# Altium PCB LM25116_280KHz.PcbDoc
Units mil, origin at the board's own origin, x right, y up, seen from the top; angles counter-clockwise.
Board outline 2245 x 1195 mil, 2 copper layers (Top Layer, Bottom Layer); 35 components, 23 nets, 91 pads, 238 vias.
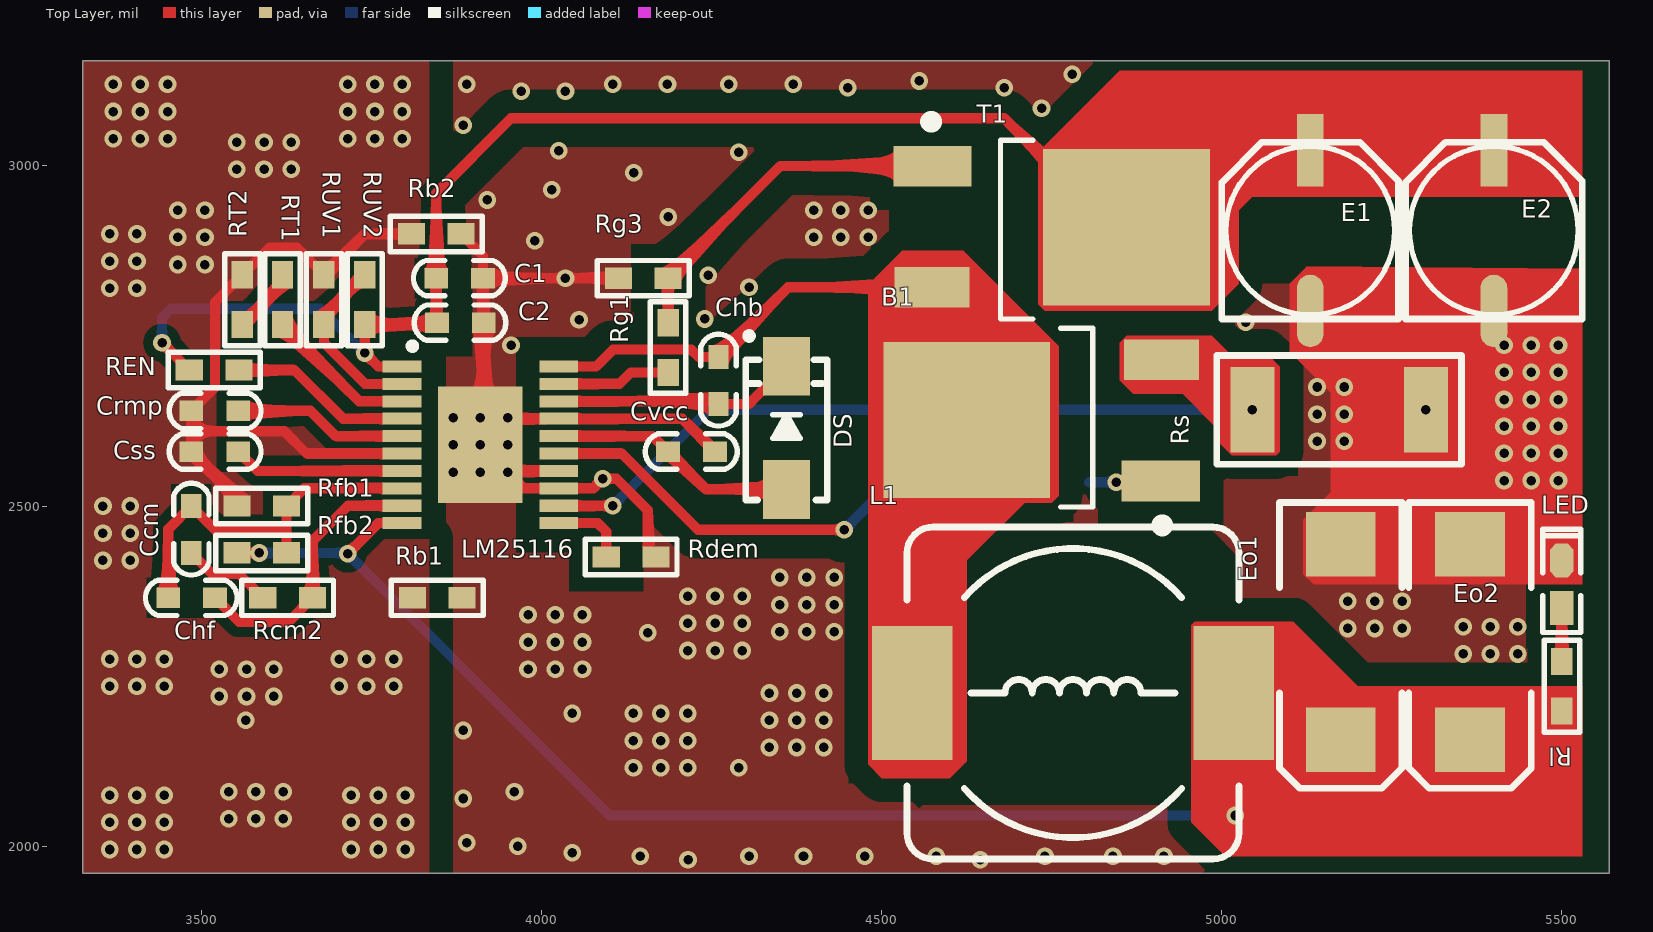
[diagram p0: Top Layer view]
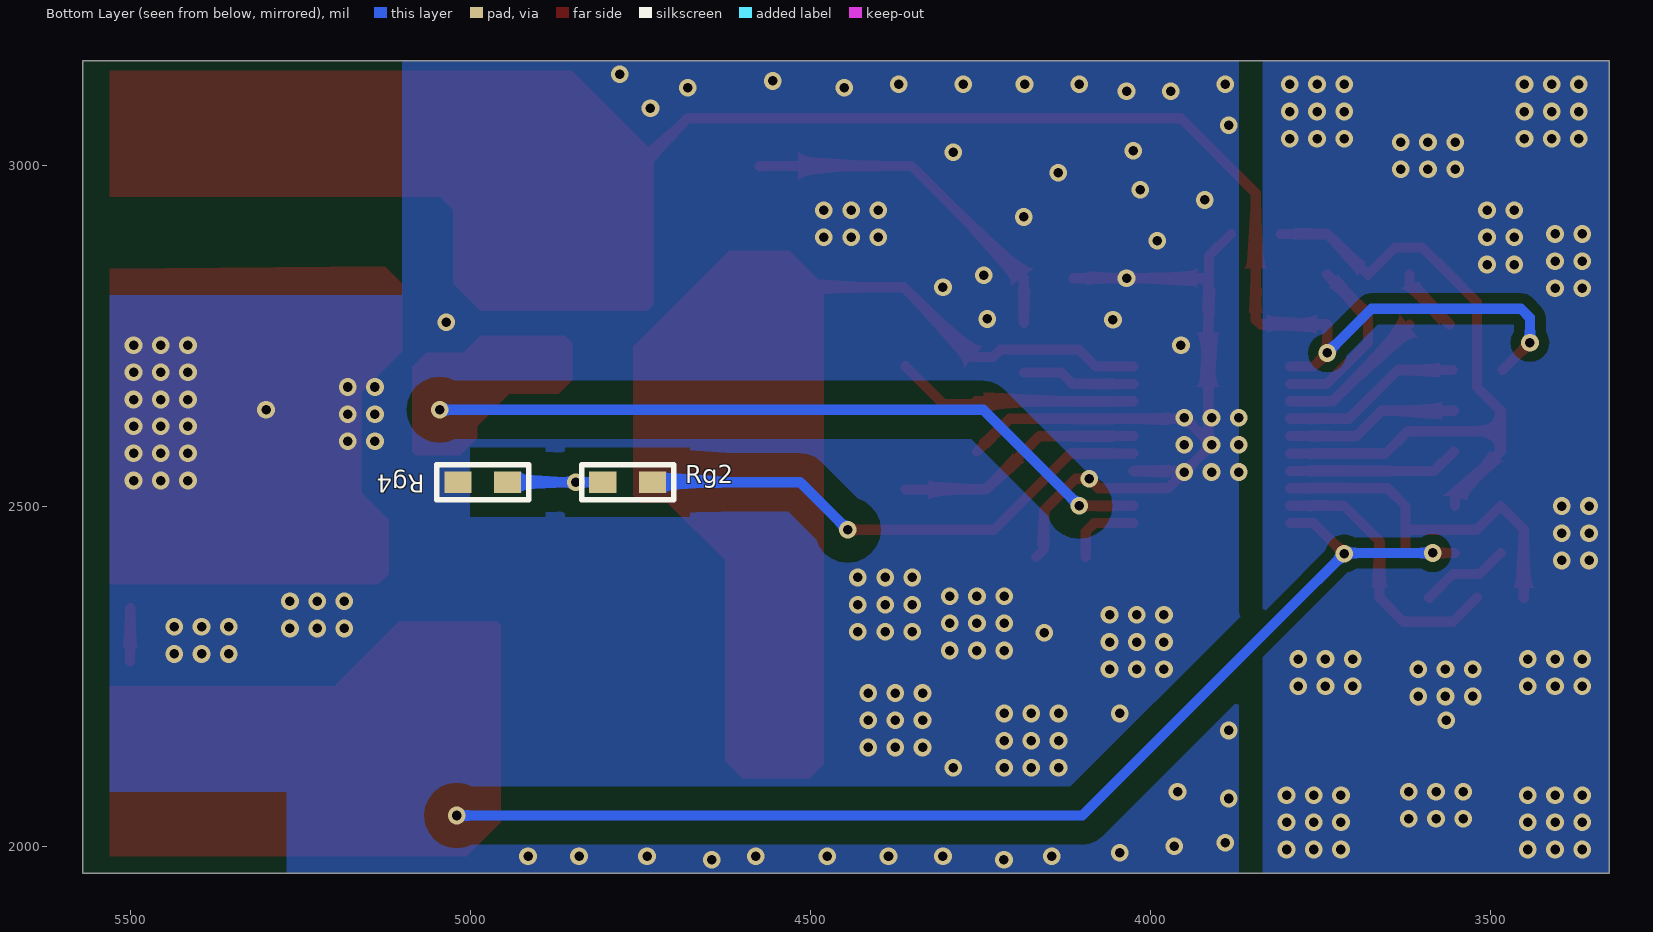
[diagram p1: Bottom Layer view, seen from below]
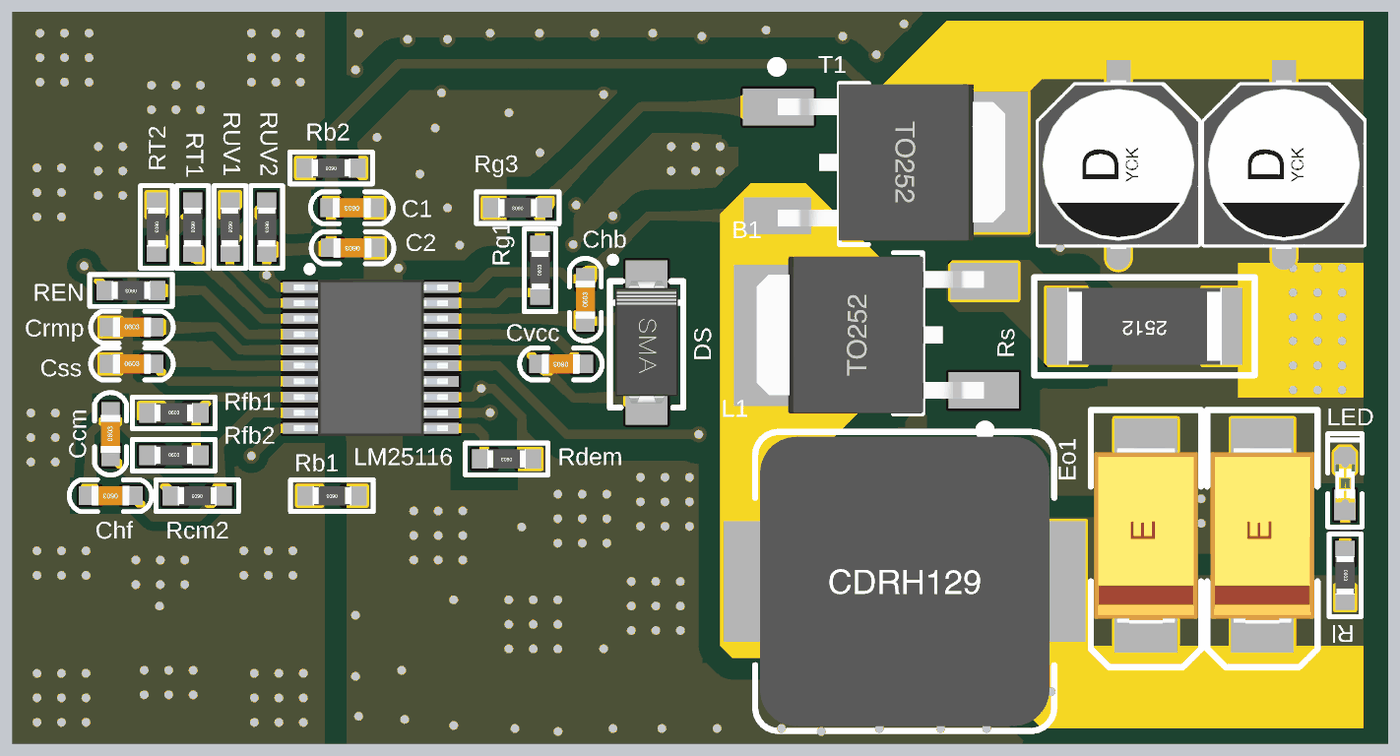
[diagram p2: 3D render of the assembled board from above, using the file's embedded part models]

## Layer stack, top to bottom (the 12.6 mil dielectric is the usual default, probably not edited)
Top Solder: solder mask 0.4, Solder Resist, Dk 3.5
Top Layer: signal copper 1.4
Dielectric 1: dielectric 12.6, FR-4, Dk 4.8
Bottom Layer: signal copper 1.4
Bottom Solder: solder mask 0.4, Solder Resist, Dk 3.5

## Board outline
3325,1960 3325,3155 5570,3155 5570,1960

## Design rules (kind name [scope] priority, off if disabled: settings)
Clearance Clearance_PGND_Ploygon [(InNamedPolygon('PGND_B') OR InNamedPolygon('PGND_T'))] p1: gap=35 ignorepadtopadclearanceinfootprint=FALSE
Clearance Clearance_AGND_Ploygon [(InNamedPolygon('AGND_B') OR InNamedPolygon('AGND_T'))] p2: gap=15 ignorepadtopadclearanceinfootprint=FALSE
Clearance Clearance_wire [All] p3: gap=5 ignorepadtopadclearanceinfootprint=FALSE
PolygonConnect [All] p1: connectstyle=Direct reliefconductorwidth=10 reliefentries=4 polygonreliefangle="90 Angle" airgapwidth=10
RoutingVias [All] p1: holewidth=28 width=50 viastyle="Through Hole" minholewidth=12 minwidth=24 maxholewidth=2800 maxwidth=5000
SolderMaskExpansion [All] p1: expansion=4
Width [All] p1: maxlimit=1000 minlimit=5 preferedwidth=10
30 further rules are at their usual default settings.

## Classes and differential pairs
polygon class PolygonClass_PGND: PGND_B PGND_T
polygon class PolygonClass_AGND: AGND_B AGND_T

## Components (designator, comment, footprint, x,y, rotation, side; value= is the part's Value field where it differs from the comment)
B1 "NTD5C668NLT4G" TO252 4790.35,2626.5 r90 top
C1 "0.1uF" "C 0603" 3879,2835 r180 top
C2 "0.1uF" "C 0603" 3880,2769.5 r180 top
Ccm "1.2nF" "C 0603" 3485,2466 r90 top
Chb "150n" "C 0603" 4260,2685 r90 top
Chf "47pF" "C 0603" 3485,2365 r180 top
Crmp "180pF" "C 0603" 3520,2640 r0 top
Css "4.7nF" "C 0603" 3520,2580 r0 top
Cvcc "330n" "C 0603" 4220,2580 r180 top
DS "SS24" SMA 4360,2615 r90 top
E1 "47uF/50V" "CM D(6.3*7.7)" 5130,2905 r90 top
E2 "47uF/50V" "CM D(6.3*7.7)" 5400,2905 r90 top
Eo1 "470uF/6.3V" "CD E(7343H)" 5175,2300 r90 top
Eo2 "470uF/6.3V" "CD E(7343H)" 5365,2300 r90 top
L1 "1uH" CDRH129 4781.22,2225 r0 top
LED "红色" "LED 0603R" 5500,2385 r90 top
LM25116 "LM25116" HSSOP20 3910,2585 r0 top
Rb1 "0" "R 0603" 3846.5,2365 r180 top
Rb2 "0" "R 0603" 3845,2900 r180 top
Rcm2 "82K" "R 0603" 3626.5,2365 r180 top
Rdem "10K" "R 0603" 4131.5,2425 r180 top
REN "1M" "R 0603" 3518.5,2700 r180 top
Rfb1 "10K" "R 0603" 3588.5,2500 r0 top
Rfb2 "32.4K" "R 0603" 3588.5,2431 r0 top
Rg1 "0" "R 0603" 4186,2733 r90 top
Rg2 "0" "R 0603" 4768.5,2535 r0 bottom
Rg3 "1M" "R 0603" 4149.5,2835 r180 top
Rg4 "1M" "R 0603" 4981.5,2535 r180 bottom
Rl "10K" "R 0603" 5500,2235 r270 top
Rs "3m" "R 2512" 5172.56,2641.5 r180 top
RT1 "10K" "R 0603" 3618.98,2803.39 r270 top
RT2 "1K" "R 0603" 3560,2803.39 r270 top
RUV1 "38.3K" "R 0603" 3679.95,2803.39 r270 top
RUV2 "180K" "R 0603" 3740,2803.39 r270 top
T1 "NTD5C668NLT4G" TO252 4694.65,2910 r270 top

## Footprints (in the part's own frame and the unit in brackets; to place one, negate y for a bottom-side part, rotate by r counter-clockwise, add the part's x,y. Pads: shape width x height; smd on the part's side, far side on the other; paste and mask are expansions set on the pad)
"C 0603" [mil] "无极性贴片电容"
  rect 35x30 smd: 1(-35,0) 2(34,0)
  silkscreen extent -67,-26 67,26, body extent -31,-16 31,16, height 32
"CD E(7343H)" [mm] "长7.3mm，宽4.3mm，厚4.0mm"
  rect 2.4x2.6 smd: 1(-3.65,0) 2(3.65,0)
  silkscreen extent -5.46,-2.29 5.21,2.29, body extent -3.65,-2.15 3.65,2.15, height 4
CDRH129 [mm] "12*12*9.5mm（长宽高）"
  rect 3x5 smd: 1(-6,0) 2(6,0)
  silkscreen extent -6.2,-6.2 6.2,6.2, body extent -6,-6 6,6, height 9.65
"CM D(6.3*7.7)" [mm] "贴片电解电容，直径6.3mm，高7.7mm"
  rect 2.7x1 smd: 1(3,0)
  oval 2.7x1 smd: 2(-3,0)
  silkscreen extent -3.3,-3.3 3.3,3.3, body extent -3.5,-3.3 3.5,3.3, height 7.7
HSSOP20 [mm]
  rect 1.45x0.45 smd: 1(-2.925,3.052) 2(-2.925,2.402) 3(-2.925,1.752) 4(-2.925,1.102) 5(-2.925,0.452) 6(-2.925,-0.198) 7(-2.925,-0.848) 8(-2.925,-1.498) 9(-2.925,-2.148) 10(-2.925,-2.798) 11(2.925,-2.798) 12(2.925,-2.148) 13(2.925,-1.498) 14(2.925,-0.848) 15(2.925,-0.198) 16(2.925,0.452) 17(2.925,1.102) 18(2.925,1.752) 19(2.925,2.402) 20(2.925,3.052)
  rect 3.15x4.35 smd: 21(0,0.127)
  silkscreen extent -2.67,3.68 -2.41,3.94, body extent -3.2,-3.12 3.2,3.38, height 1.1
"LED 0603R" [mil] "红色0603LED"
  rect 50x35 smd: 1(-35,0.26)
  oct 50x35 smd: 2(35,0.26)
  silkscreen extent -71,-28 81,28, body extent -31,-16 32,16, height 24
"R 0603" [mil] "1/10W贴片电阻"
  rect 40x31.5 smd: 1(-36.5,0) 2(36.5,0)
  silkscreen extent -68,-26 68,26, body extent -31,-16 32,16, height 16
"R 2512" [mm] "1W贴片电阻"
  rect 1.65x3.2 smd: 1(-3.24,0) 2(3.24,0)
  silkscreen extent -4.57,-2.03 4.57,2.03, body extent -3.2,-1.6 3.2,1.6, height 0.55
SMA [mm] "4.5x2.6*2.2mm（长宽高，不包括引脚）"
  rect 2.2x1.75 smd: 1(-2.3,0) 2(2.3,0)
  silkscreen extent -2.7,-1.52 3.56,1.52, body extent -2.53,-1.3 2.58,1.3, height 2.15
TO252 [mil] "252晶体管"
  rect 60x115 smd: 1(-89.55,-119.77)
  rect 230x245 smd: 2(0,165.35)
  rect 60x110 smd: 3(88.45,-120.77)
  silkscreen extent -156,-123 135,28, body extent -127,-120 129,251, height 91

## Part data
B1 T1: library part 2SK3615, "N沟场效应管"
C1 C2 Ccm Chb Chf Crmp Css Cvcc: library part C, "无极性贴片电容"
DS: library part SS14, "肖特基二极管"
E1 E2: library part C-CM, "贴片电解电容"
Eo1 Eo2: library part C-CD, "贴片钽电容"
L1: library part L-CDRH, "功率屏蔽电感"
LED: library part LED-SMD, "贴片LED"
LM25116: "42V 宽输入电压同步降压控制器"
Rb1 Rb2 Rcm2 Rdem REN Rfb1 Rfb2 Rg1 Rg2 Rg3 Rg4 Rl Rs RT1 RT2 RUV1 RUV2: library part R, "贴片电阻"

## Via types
v1: diameter 26, hole 14, Top Layer to Bottom Layer, tented both sides, 238 vias

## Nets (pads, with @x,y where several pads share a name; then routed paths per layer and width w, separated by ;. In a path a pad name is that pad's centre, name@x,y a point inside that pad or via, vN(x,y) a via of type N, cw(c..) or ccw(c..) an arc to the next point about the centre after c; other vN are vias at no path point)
+5: Eo1.1 Eo2.1 L1.2 LM25116.10 Rfb2.1 Rl.2 | length 1726.3
  Top Layer w15: Rfb2.1 v1(3585,2431) ; v1(3715,2430) 3759.84,2474.84 LM25116.10
  Bottom Layer w15: v1(3585,2431) 3714,2431 v1(3715,2430) 3795,2350 4100,2045 v1(5020,2045)
AGND: Crmp.1 Css.1 LM25116.6 Rb1.2 Rb2.2 Rfb1.1 RT2.1 RUV1.1 | length 1028.8
  Top Layer w15: Rfb1.1 3552,2513 Css.1 3485,2610 ; LM25116.6 3654.3,2577.2 3621.5,2610 3485,2610 ; Rb2.2 3740.06,2900 RUV1.1 3639.84,2880 3600.11,2880 RT2.1 3520,2799.89 3520,2675 Crmp.1 3485,2610
  other v1: 3365,1995 3405,1995 3445,1995 3719.84,1995 3759.84,1995 3799.84,1995 3365,2035 3405,2035 3445,2035 3719.84,2035 3759.84,2035 3799.84,2035 3540,2040 3580,2040 3620,2040 3365,2075 3405,2075 3445,2075 3719.84,2075 3759.84,2075 3799.84,2075 3540,2080 3580,2080 3620,2080 3565,2185 3526.16,2220 3566.16,2220 3606.16,2220 3365,2235 3405,2235 3445,2235 3702.6,2235 3742.6,2235 3782.6,2235 3526.16,2260 3566.16,2260 3606.16,2260 3365,2275 3405,2275 3445,2275 3702.6,2275 3742.6,2275 3782.6,2275 3355,2420 3395,2420 3355,2460 3395,2460 3355,2500 3395,2500 3365,2820 3405,2820 3465,2855 3505,2855 3365,2860 3405,2860 3465,2895 3505,2895 3365,2900 3405,2900 3465,2935 3505,2935 3551.89,2995 3591.89,2995 3631.89,2995 3551.89,3035 3591.89,3035 3631.89,3035 3370,3040 3410,3040 3450,3040 3715,3040 3755,3040 3795,3040 3370,3080 3410,3080 3450,3080 3715,3080 3755,3080 3795,3080 3370,3120 3410,3120 3450,3120 3715,3120 3755,3120 3795,3120
COMP: Chf.1 LM25116.9 Rcm2.1 | length 408.6
  Top Layer w15: Chf.1 3555,2330 3628,2330 Rcm2.1 3663,2448.13 3715.31,2500.43 LM25116.9
CS: B1.3 LM25116.12 Rs.2 | length 1078.3
  Top Layer w15: LM25116.12 v1(4104.57,2500.43)
  Bottom Layer w15: v1(4104.57,2500.43) 4245.63,2641.5 v1(5045,2641.5)
CSG: C1.1 C2.1 Cvcc.1 E1.2 E2.2 Eo1.2 Eo2.2 LED.2 LM25116.13 LM25116.14 LM25116.17 LM25116.21 Rb1.1 Rb2.1 Rdem.1 Rg3.2 Rg4.1 Rs.1 | length 1346.9
  Top Layer w15: Rb2.1 3914,2867.5 C1.1 ; LM25116.14 LM25116.21@3948.39,2551.61 ; Rg3.2 v1(4035,2835) C1.1 ; Rdem.1 4156.19,2436.81 4156.19,2493.81 4110,2540 v1(4090,2540) 4076.02,2526.02 LM25116.13 3973.98,2526.02 v1(3950,2550) LM25116.21@3948.39,2551.61 ; Cvcc.1 4206.61,2628.39 LM25116.17 3948.39,2628.39 LM25116.21@3915,2595 ; C1.1 3914,2770.5 C2.1 LM25116.21@3915,2595 ; LM25116.21@3915,2595 v1(3910,2590) LM25116.21@3948.39,2551.61
  other v1: 4215.32,1980 4645,1980 4145,1985 4305,1985 4385,1985 4475,1985 4580,1985 4740,1985 4840,1985 4915,1985 4045,1990 3965,2000 3890,2005 3885,2070 3960,2080 4135,2115 4175,2115 4215,2115 4290,2115 4335,2145 4375,2145 4415,2145 4135,2155 4175,2155 4215,2155 3885,2170 4335,2185 4375,2185 4415,2185 4045,2195 4135,2195 4175,2195 4215,2195 4335,2225 4375,2225 4415,2225 3980,2260 4020,2260 4060,2260 5355,2282.5 5395,2282.5 5435,2282.5 4215,2287.5 4255,2287.5 4295,2287.5 3980,2300 4020,2300 4060,2300 4156.19,2313.78 4350,2314.96 4390,2314.96 4430,2314.96 5185,2320 5225,2320 5265,2320 5355,2322.5 5395,2322.5 5435,2322.5 4215,2327.5 4255,2327.5 4295,2327.5 3980,2340 4020,2340 4060,2340 4350,2354.96 4390,2354.96 4430,2354.96 5185,2360 5225,2360 5265,2360 4215,2367.5 4255,2367.5 4295,2367.5 4350,2394.96 4390,2394.96 4430,2394.96 5415,2537.5 5455,2537.5 5495,2537.5 3870,2550 3910,2550 5415,2577.5 5455,2577.5 5495,2577.5 3870,2590 3950,2590 5140,2595 5180,2595 5415,2617.5 5455,2617.5 5495,2617.5 3870,2630 3910,2630 3950,2630 5140,2635 5180,2635 5300.12,2641.5 5415,2656.5 5455,2656.5 5495,2656.5 5140,2675 5180,2675 5415,2696.5 5455,2696.5 5495,2696.5 3955,2736.5 5415,2736.5 5455,2736.5 5495,2736.5 5035,2770 4055,2774 4240,2775 4305,2821.55 4245,2839.39 3990,2890 4400,2895 4440,2895 4480,2895 4186,2925 4400,2935 4440,2935 4480,2935 3920,2950 4015,2965 4135.25,2990 4290,3020 4025.16,3022.51 3885,3060 4735,3085 3970,3110 4035,3110 4450,3115 4680,3115 3890,3120 4104.57,3120 4185,3120 4275,3120 4370,3120 4555,3125 4780,3135
DEMB: LM25116.11 Rdem.2 | length 112.5
  Top Layer w15: LM25116.11 4082.66,2474.84 4095,2462.5 Rdem.2
EN: LM25116.4 REN.1 | length 269.5
  Top Layer w15: REN.1 3636.5,2700 3708.11,2628.39 LM25116.4
FB: Ccm.2 Chf.2 LM25116.8 Rfb1.2 Rfb2.2 | length 553.4
  Top Layer w15: Chf.2 3451,2466 Ccm.2 3520,2465 3624.5,2465 3625,2465.5 ; Rfb2.2 3625,2465.5 ; LM25116.8 3651.02,2526.02 Rfb1.2 3625,2465.5
HB: Chb.1 DS.2 LM25116.18 | length 359.5
  Top Layer w15: LM25116.18 4256.02,2653.98 Chb.1 4304.45,2650 DS.2
HO: LM25116.19 Rg1.1 | length 167.9
  Top Layer w15: LM25116.19 4114.57,2679.57 4131.5,2696.5 Rg1.1
LO: LM25116.15 Rg2.1 | length 782.3
  Top Layer w15: LM25116.15 4117.8,2577.2 4230,2465 v1(4445,2465)
  Bottom Layer w15: v1(4445,2465) 4515,2535 Rg2.1
NetB1_1: B1.1 Rg2.2 Rg4.2 | length 205.9
  Top Layer w15: v1(4845,2535) 4908.18,2535 B1.1
  Bottom Layer w15: Rg2.2 v1(4845,2535) Rg4.2
NetCcm_1: Ccm.1 Rcm2.2 | length 132.3
  Top Layer w15: Ccm.1 3516,2400 3555,2400 Rcm2.2
NetLED_1: LED.1 Rl.1 | length 79.1
  Top Layer w15: LED.1 5499.74,2286.24 5500,2286.5 Rl.1
NetRg1_2: Rg1.2 Rg3.1 T1.1 | length 522.9
  Top Layer w15: Rg1.2 Rg3.1 4351,3000 4574.43,3000 T1.1
NetRT1_1: RT1.1 RT2.2 | length 97.4
  Top Layer w15: RT2.2 3618.98,2825.87 RT1.1
RAMP: Crmp.2 LM25116.5 | length 256.3
  Top Layer w15: Crmp.2 3660,2640 3697.2,2602.8 LM25116.5
RT/SYNC: LM25116.3 RT1.2 | length 222.6
  Top Layer w15: RT1.2 3731.89,2653.98 LM25116.3
SS: Css.2 LM25116.7 | length 252.6
  Top Layer w15: Css.2 3582.39,2551.61 LM25116.7
SW: B1.2 Chb.2 L1.1 LM25116.20 T1.3 | length 606
  Top Layer w15: LM25116.20 4080.16,2705.16 4105,2730 4220,2730 4231,2719 Chb.2 4362.55,2821.55 T1.3
UVLO: LM25116.2 RUV1.2 RUV2.1 | length 264.7
  Top Layer w15: RUV2.1 3679.95,2779.84 RUV1.2 3679.95,2740 3740.38,2679.57 LM25116.2
VCC: C1.2 C2.2 E1.1 E2.1 LM25116.1 REN.2 RUV2.2 T1.2 | length 1949.6
  Top Layer w15: v1(3442,2740) REN.2 ; LM25116.1 3759.84,2705.16 v1(3740,2725) RUV2.2 3837.89,2766.89 3845,2774 C1.2 3845,2960 3955,3070 4680,3070 4840,2910 T1.2
  Bottom Layer w15: v1(3442,2740) 3442,2777 3455,2790 3675,2790 v1(3740,2725)
VCC_G: Cvcc.2 DS.1 LM25116.16 | length 367.3
  Top Layer w15: LM25116.16 4163.2,2602.8 Cvcc.2 4241.55,2524.45 DS.1

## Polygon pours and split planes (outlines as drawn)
CSG on Top Layer "PGND_T" (solid, remove dead copper, pour order 4): 3860,3155 3860,1960 5530,1960 5530,3155
AGND on Top Layer "AGND_T" (solid, remove dead copper, pour order 0): 3325,3155 3325,1960 3835,1960 3835,3155
CSG on Bottom Layer "PGND_B" (solid, remove dead copper, pour order 6): 3860,3155 3860,1960 5530,1960 5530,3155
AGND on Bottom Layer "AGND_B" (solid, remove dead copper, pour order 2): 3325,3155 3325,1960 3835,1960 3835,3155

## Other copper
Top Layer:
  pour cut-out: 5060.3,2919.7 5060.3,2826.89 5530,2826.89 5530,2919.7
  pour cut-out: 5060.3,2919.7
  pour cut-out: 4510,3035 4510,2845 4710,2845 4710,3035
  pour cut-out: 4545,2426 4545,2065 4555,2055 4560,2060 4995,2060 5025,2090 5025,2425 4985,2465 4583.86,2465
  region net AGND: 3325,3155
  region net CSG: 5125,2852.5 5125,2851.89 5100,2826.89 5100,2726.5 5160,2666.5 5160,2520 5120,2480 5120,2400 5135,2385 5530,2385 5530,2849.07
  region net +5: 4960,2330 4955,2325 4955,2035 5005,1985 5530,1985 5530,2235 5200,2235 5105,2330
  region net CS: 4860,2750 4850,2740 4850,2685 4870,2665 4942.36,2665 4990,2617.36 4990,2600 5015,2575 5080,2575 5085,2580 5085,2705 5065,2725 5010,2725 4985,2750
  region net VCC: 4730,3020 4730,2796.89 4740,2786.89 4985,2786.89 5025,2826.89 5025,2935 5045,2955 5530,2955 5530,3140 4850,3140
  region net SW: 4530,2875 4480,2825 4480,2120 4500,2100 4600,2100 4625,2125 4625,2420 4710,2505 4750,2505 4760,2515 4760,2735 4620,2875
Bottom Layer:
  pour cut-out: 5540,2080 5270,2080 5270,1960 5540,1960
  pour cut-out: 5535,3155 5100,3155 5100,2810 5535,2810

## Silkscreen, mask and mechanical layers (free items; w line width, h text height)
Top Solder:
  rectangle: 5325,2525 5530,2745
  rectangle: 5030,1985 5530,2080
  rectangle: 4990,3045 5530,3140
  region: 4760,2515 4750,2505 4710,2505 4625,2420 4625,2125 4600,2100 4500,2100 4480,2120 4480,2825 4530,2875 4620,2875 4760,2735
  region: 4760,2515
  region: 4755,2505
  region: 4530,2880
  region: 4955,2135 4955,2035 5005,1985 5530,1985 5530,2120 5085,2120 5070,2135
  region: 5010,3140 4850,3140 4735,3025 4737.49,3022.51 4982.51,3022.51 5010,3050
Mechanical 1:
  the board outline again, w10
